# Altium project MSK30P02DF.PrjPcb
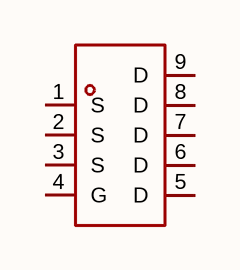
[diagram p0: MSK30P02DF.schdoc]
1 sheet, 1 parts. Net scope: global (net labels, ports and power ports of the same name join across sheets).

## Sheet MSK30P02DF.schdoc
size 127 x 101 mm

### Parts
Q?  msk30p02df  [DFN-8_L3.0-W3.0-P0.65-BL]  (value not drawn)

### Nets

Not connected (* = marked no-connect by the designer): Q? 1(S) 2(S) 3(S) 4(G) 5(D) 6(D) 7(D) 8(D) 9(D)

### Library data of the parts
Q? = msk30p02df: 数量:1个P沟道;漏源电压(Vdss):20V;连续漏极电流(Id):30A;导通电阻(RDS(on)):15mΩ@4.5V;耗散功率(Pd):18W;阈值电压(Vgs(th)):1V;; Manufacturer: MSKSEMI(美森科); AddInBom: yes; ModelId: 8b850663669847e9b39b8fc804d68d4b; ModelName: DFN-8_L3.0-W3.0-H0.7-P0.65; ModelTransform: 118.8974,118.11,0,90,0,0,0,0,0; Number: 1个P沟道; Drain to Source Voltage: 20V; Current - Continuous Drain(Id): 30A; Pd - Power Dissipation: 18W; Gate Threshold Voltage (Vgs(th)): 1V; Gate Charge(Qg): 35nC@4.5V; Input Capacitance(Ciss): 2.8nF; Reverse Transfer Capacitance (Crss@Vds): 590pF; Type: P沟道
